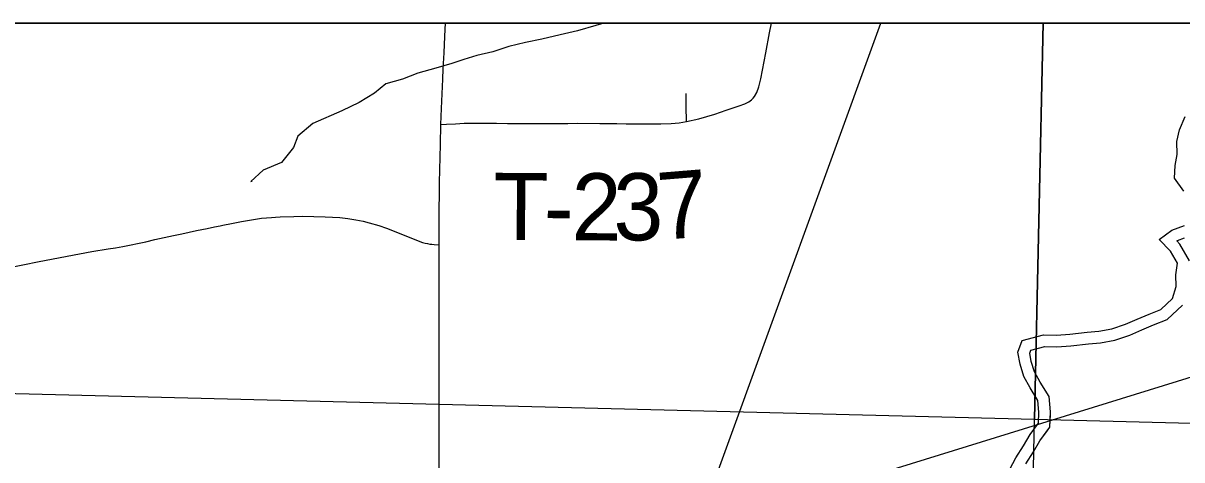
# Model space of a CAD drawing. Extents: x 0 to 34, y 0 to 22.
# Drawn here: x 6.588 to 7.568, y 20.531 to 20.9 of the extents above; entities that cross this region are included whole.
import ezdxf

# ---------------------------------------------------------------- set-up
doc = ezdxf.new("R2010")
doc.units = 0
for name, color, linetype in [('GM_X_Corporation', 7, 'Continuous'), ('GM_X_Major_River', 7, 'Continuous'), ('GM_X_Minor_River', 7, 'Continuous'), ('GM_X_Rail_Line', 7, 'Continuous'), ('GM_X_State_Route', 7, 'Continuous'), ('GM_X_Township_Road', 7, 'Continuous'), ('GM_X_Township_Road_Text', 7, 'Continuous'), ('SH_Data', 7, 'Continuous')]:
    doc.layers.add(name, color=color, linetype=linetype)

msp = doc.modelspace()

# ---------------------------------------------------------------- linework, layer by layer
at = {"layer": 'GM_X_Corporation'}
for points in [[(8.9, 20.9), (2.1, 20.9), (2.1, 15.66063)], [(8.9, 20.9), (3.38863, 20.9), (3.38695, 20.7918), (3.37239, 19.72632), (3.36907, 19.50411), (3.36418, 18.70055)]]:
    msp.add_lwpolyline(points, dxfattribs=at)
for points in [[(7.45088, 20.9), (6.4439, 20.9), (6.43656, 20.5905), (7.44368, 20.56496)], [(8.47026, 20.9), (7.45088, 20.9), (7.44368, 20.56496), (8.46216, 20.53916)], [(8.46216, 20.53916), (8.44047, 19.52563), (7.42308, 19.55263), (7.44368, 20.56496)]]:
    msp.add_lwpolyline(points, close=True, dxfattribs=at)
at = {"layer": 'GM_X_Major_River'}
for points in [[(7.57, 20.75804), (7.56196, 20.76894), (7.56263, 20.77956), (7.56443, 20.78905), (7.56396, 20.80003), (7.56614, 20.80991), (7.57096, 20.82095)], [(7.44696, 20.56162), (7.44726, 20.57109), (7.44642, 20.58094), (7.4399, 20.59148), (7.43452, 20.60127), (7.43141, 20.61147), (7.42943, 20.62168), (7.43312, 20.63157), (7.45123, 20.63631), (7.46219, 20.63604), (7.47352, 20.63692), (7.48825, 20.63859), (7.49807, 20.63945), (7.50902, 20.64146), (7.5207, 20.64537), (7.53049, 20.64964), (7.54067, 20.65391), (7.55046, 20.6578), (7.56021, 20.667), (7.56352, 20.67727), (7.56306, 20.68711), (7.56448, 20.69698), (7.55872, 20.70715), (7.54919, 20.7169), (7.5597, 20.72497), (7.57063, 20.72887)], [(7.57469, 20.6989), (7.56665, 20.7131), (7.56397, 20.71585), (7.56446, 20.71623), (7.57045, 20.71837)], [(7.57469, 20.6989), (7.56665, 20.7131), (7.56397, 20.71585), (7.56446, 20.71623), (7.57045, 20.71837)], [(7.45679, 20.56131), (7.4571, 20.57136), (7.45601, 20.58411), (7.44839, 20.59643), (7.44363, 20.60511), (7.44096, 20.61385), (7.43961, 20.62083), (7.44055, 20.62335), (7.45238, 20.62645), (7.46245, 20.6262), (7.47446, 20.62713), (7.48924, 20.62881), (7.49939, 20.6297), (7.51148, 20.63191), (7.52424, 20.63618), (7.53436, 20.6406), (7.54439, 20.64481), (7.55584, 20.64936), (7.56879, 20.66158)], [(7.4567, 20.55823), (7.4571, 20.57136), (7.45601, 20.58411), (7.44839, 20.59643), (7.44363, 20.60511), (7.44096, 20.61385), (7.43961, 20.62083), (7.44055, 20.62335), (7.45238, 20.62645), (7.46245, 20.6262), (7.47446, 20.62713), (7.48924, 20.62881), (7.49939, 20.6297), (7.51148, 20.63191), (7.52424, 20.63618), (7.53436, 20.6406), (7.54439, 20.64481), (7.55584, 20.64936), (7.56879, 20.66158)], [(7.42273, 20.52272), (7.42794, 20.53225), (7.43428, 20.54254), (7.43987, 20.55207), (7.44696, 20.56162)], [(7.43645, 20.52731), (7.4427, 20.53748), (7.44807, 20.54664), (7.4567, 20.55823)], [(7.43645, 20.52731), (7.4427, 20.53748), (7.44807, 20.54664), (7.45485, 20.55576)]]:
    msp.add_lwpolyline(points, dxfattribs=at)
at = {"layer": 'GM_X_Minor_River'}
msp.add_lwpolyline([(7.0795, 20.9), (7.0728, 20.89796), (7.05734, 20.89363), (7.04262, 20.89006), (7.02716, 20.88649), (7.01319, 20.88369), (6.99924, 20.88013), (6.98567, 20.87582), (6.97209, 20.87265), (6.96115, 20.86913), (6.95097, 20.86598), (6.9374, 20.86205), (6.92232, 20.85773), (6.90913, 20.85266), (6.89518, 20.84873), (6.88542, 20.84067), (6.87263, 20.83295), (6.85795, 20.82598), (6.83348, 20.81511), (6.82072, 20.80437), (6.81702, 20.79486), (6.80692, 20.78225), (6.79148, 20.77564), (6.78098, 20.76606), (6.78211, 20.76645)], dxfattribs=at)
at = {"layer": 'GM_X_Rail_Line'}
msp.add_line((7.17641, 20.52214), (7.31378, 20.9), dxfattribs=at)
msp.add_lwpolyline([(7.15378, 20.47014), (7.70298, 20.6401), (7.7933, 20.66371), (7.88362, 20.68116), (8.21721, 20.73452), (8.32292, 20.74991), (8.41735, 20.7612), (8.48817, 20.76325), (8.54976, 20.76632), (8.58903, 20.77378), (8.66693, 20.80326), (8.71799, 20.81574), (8.9, 20.84057)], dxfattribs=at)
at = {"layer": 'GM_X_State_Route'}
for points in [[(6.94166, 20.8143), (6.94213, 20.82787), (6.94322, 20.85264), (6.94371, 20.86131), (6.94444, 20.87495), (6.94502, 20.88859), (6.94525, 20.89478), (6.9455, 20.9)], [(6.94018, 20.71244), (6.94026, 20.73292), (6.94043, 20.76513), (6.94123, 20.79728), (6.94166, 20.8143)], [(6.90827, 20.2385), (6.90863, 20.24046), (6.91799, 20.29243), (6.92802, 20.3506), (6.93344, 20.38369), (6.93552, 20.39906), (6.93722, 20.41509), (6.93835, 20.42931), (6.93929, 20.44853), (6.93993, 20.47025), (6.94013, 20.49384), (6.9402, 20.53795), (6.94026, 20.59013), (6.94022, 20.61748), (6.94036, 20.65661), (6.9403, 20.67586), (6.94013, 20.6982), (6.94018, 20.71244)]]:
    msp.add_lwpolyline(points, dxfattribs=at)
at = {"layer": 'GM_X_Township_Road'}
for points in [[(7.14939, 20.81684), (7.15968, 20.81921), (7.17346, 20.82314), (7.18288, 20.82636), (7.19402, 20.83012), (7.19877, 20.83181), (7.20221, 20.83355), (7.20434, 20.83507), (7.20576, 20.83645), (7.20693, 20.83805), (7.20875, 20.84142), (7.21049, 20.84617), (7.21223, 20.85282), (7.21634, 20.87477), (7.21956, 20.89182), (7.22128, 20.9)], [(7.14939, 20.81684), (7.1493, 20.82043), (7.14918, 20.82595), (7.14923, 20.83211), (7.14915, 20.83875), (7.14921, 20.84044)], [(6.94018, 20.71244), (6.94026, 20.73292), (6.94043, 20.76513), (6.94123, 20.79728), (6.94166, 20.8143)], [(6.94166, 20.8143), (6.94632, 20.81451), (6.95408, 20.81496), (6.96146, 20.8154), (6.97383, 20.81544), (6.98872, 20.8153), (6.99804, 20.81527), (7.01977, 20.81522), (7.03591, 20.81516), (7.04892, 20.81521), (7.05694, 20.81535), (7.07615, 20.81511), (7.09041, 20.81506), (7.09847, 20.81497), (7.11523, 20.81476), (7.12767, 20.8148), (7.13639, 20.81514), (7.14325, 20.81573), (7.14939, 20.81684)], [(6.58117, 20.6943), (6.5897, 20.69596), (6.60066, 20.69814), (6.62566, 20.70286), (6.6464, 20.70675), (6.66042, 20.70906), (6.66654, 20.71004), (6.67264, 20.71119), (6.69207, 20.71516), (6.69989, 20.71698), (6.71557, 20.72046), (6.72263, 20.72194), (6.73506, 20.72464), (6.74413, 20.72629), (6.75015, 20.72763), (6.75499, 20.72868), (6.75739, 20.72922), (6.76468, 20.73063), (6.77306, 20.73228), (6.78149, 20.73369), (6.78992, 20.73496), (6.79842, 20.73571), (6.80177, 20.73596), (6.80574, 20.73609), (6.81729, 20.73659), (6.8247, 20.73677), (6.84391, 20.73626), (6.85631, 20.73557), (6.86309, 20.73477), (6.86986, 20.73369), (6.87585, 20.73249), (6.88096, 20.73123), (6.88911, 20.72882), (6.89559, 20.72668), (6.9037, 20.72352), (6.91978, 20.71688), (6.92622, 20.71461), (6.92838, 20.71404), (6.93042, 20.71351), (6.93233, 20.71318), (6.9341, 20.71296), (6.93588, 20.71274), (6.94018, 20.71244)]]:
    msp.add_lwpolyline(points, dxfattribs=at)
at = {"layer": 'SH_Data'}
msp.add_line((2.1, 20.9), (8.9, 20.9), dxfattribs=at)

# ---------------------------------------------------------------- texts
at = {"layer": 'GM_X_Township_Road_Text'}
for s, rotation, p in [('T', 359.67429, (6.9861, 20.71663)), ('2', 359.82554, (7.0521, 20.71627)), ('3', 0.3059, (7.08762, 20.71616)), ('7', 4.6485, (7.12731, 20.71655)), ('-', 359.70166, (7.02863, 20.71639))]:
    msp.add_text(s, height=0.05682, rotation=rotation, dxfattribs=at).set_placement(p)

doc.saveas('drawing.dxf')
